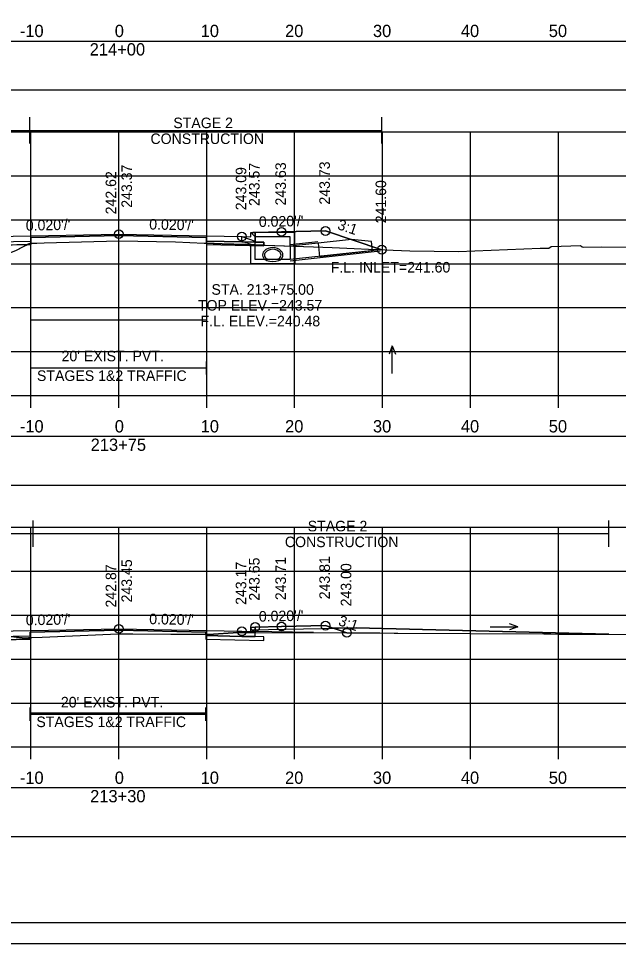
# Model space of a CAD drawing. Extents: x 1369627 to 1374022, y 380035 to 398173.
# Drawn here: x 1372087.1 to 1372155.4, y 383027.1 to 383132.4 of the extents above; entities that cross this region are included whole.
import ezdxf

# ---------------------------------------------------------------- set-up
doc = ezdxf.new("R2010")
doc.units = 0
for name, color, linetype in [('Default', 7, 'Continuous'), ('R_Alt Surface', 7, 'Continuous'), ('R_Axis', 7, 'Continuous'), ('R_Axis Annot', 7, 'Continuous'), ('R_Border', 7, 'Continuous'), ('R_Border Notes', 7, 'Continuous'), ('R_Drive', 7, 'Continuous'), ('R_Exist Surface', 7, 'Continuous'), ('R_Fin Surface', 7, 'Continuous'), ('R_Grid', 7, 'Continuous'), ('R_MOT', 7, 'Continuous'), ('R_No Plot', 7, 'Continuous'), ('R_Water', 7, 'Continuous'), ('R_Water Annot', 7, 'Continuous'), ('R_Xsect Elev', 7, 'Continuous'), ('R_Xsect Slope', 7, 'Continuous'), ('T_Vehicle Path Lt Minor', 7, 'Continuous'), ('T_Vehicle Path Rt', 7, 'Continuous')]:
    doc.layers.add(name, color=color, linetype=linetype)

msp = doc.modelspace()

# ---------------------------------------------------------------- linework, layer by layer
at = {"layer": 'Default'}
for p, q in [((1372088.52, 383091.88), (1372088.52, 383093.38)), ((1372108.52, 383091.88), (1372108.52, 383093.38)), ((1372088.52, 383092.63), (1372108.52, 383092.63)), ((1372088.44, 383052.48), (1372088.44, 383053.98)), ((1372088.44, 383053.23), (1372108.44, 383053.23)), ((1372108.44, 383052.48), (1372108.44, 383053.98))]:
    msp.add_line(p, q, dxfattribs=at)
for points in [[(1371948.53, 383124.28), (1372248.53, 383124.28), (1372248.53, 383129.8), (1371948.53, 383129.8)], [(1371948.53, 383079.29), (1372248.53, 383079.29), (1372248.53, 383084.81), (1371948.53, 383084.81)], [(1371948.53, 383039.31), (1372248.53, 383039.31), (1372248.53, 383044.83), (1371948.53, 383044.83)]]:
    msp.add_lwpolyline(points, close=True, dxfattribs=at)
at = {"layer": 'R_Alt Surface'}
for points in [[(1372083.03, 383108.06), (1372083.03, 383106.96), (1372084.53, 383106.99), (1372088.52, 383107.07), (1372088.52, 383107.49), (1372098.53, 383107.69), (1372108.52, 383107.49), (1372108.52, 383107.07), (1372112.53, 383106.99), (1372114.03, 383106.96), (1372114.03, 383108.06)], [(1372083.03, 383063.14), (1372083.03, 383062.05), (1372084.53, 383062.08), (1372088.44, 383062.15), (1372088.44, 383062.57), (1372098.53, 383062.77), (1372108.44, 383062.57), (1372108.44, 383062.16), (1372112.53, 383062.08), (1372114.03, 383062.05), (1372114.03, 383063.14)]]:
    msp.add_lwpolyline(points, dxfattribs=at)
for points in [[(1372082.03, 383106.94), (1372083.03, 383106.96), (1372084.53, 383106.99), (1372088.52, 383107.07), (1372088.52, 383106.66), (1372082.03, 383106.53)], [(1372115.03, 383106.94), (1372114.03, 383106.96), (1372112.53, 383106.99), (1372108.52, 383107.07), (1372108.52, 383106.66), (1372115.03, 383106.53)], [(1372082.03, 383062.03), (1372083.03, 383062.05), (1372084.53, 383062.08), (1372088.44, 383062.15), (1372088.44, 383061.74), (1372082.03, 383061.61)], [(1372115.03, 383062.03), (1372114.03, 383062.05), (1372112.53, 383062.08), (1372108.44, 383062.16), (1372108.44, 383061.74), (1372115.03, 383061.61)]]:
    msp.add_lwpolyline(points, close=True, dxfattribs=at)
at = {"layer": 'R_Axis'}
for p, q in [((1371948.53, 383089.49), (1372248.53, 383089.49)), ((1372088.53, 383088.09), (1372088.53, 383089.49)), ((1372098.53, 383088.09), (1372098.53, 383089.49)), ((1372108.53, 383088.09), (1372108.53, 383089.49)), ((1372118.53, 383088.09), (1372118.53, 383089.49)), ((1372128.53, 383088.09), (1372128.53, 383089.49)), ((1372138.53, 383088.09), (1372138.53, 383089.49)), ((1372148.53, 383088.09), (1372148.53, 383089.49)), ((1371948.53, 383049.49), (1372248.53, 383049.49)), ((1372088.53, 383048.09), (1372088.53, 383049.49)), ((1372098.53, 383048.09), (1372098.53, 383049.49)), ((1372108.53, 383048.09), (1372108.53, 383049.49)), ((1372118.53, 383048.09), (1372118.53, 383049.49)), ((1372128.53, 383048.09), (1372128.53, 383049.49)), ((1372138.53, 383048.09), (1372138.53, 383049.49)), ((1372148.53, 383048.09), (1372148.53, 383049.49))]:
    msp.add_line(p, q, dxfattribs=at)
at = {"layer": 'R_Border'}
msp.add_line((1372256.71, 383029.49), (1371940.53, 383029.49), dxfattribs=at)
at = {"layer": 'R_Drive'}
for points in [[(1372113.53, 383062.64), (1372113.53, 383062.81), (1372125.53, 383063.05)], [(1372125.53, 383063.05), (1372154.26, 383062.31)]]:
    msp.add_lwpolyline(points, dxfattribs=at)
at = {"layer": 'R_Exist Surface'}
for points in [[(1372086.91, 383106.04), (1372088.12, 383106.66), (1372088.4, 383106.81), (1372090.04, 383106.85), (1372098.52, 383107.11), (1372104.96, 383106.97), (1372108.23, 383106.84), (1372110.29, 383106.76), (1372112.97, 383106.67), (1372120.68, 383106.41), (1372122.81, 383106.34), (1372125.31, 383106.22), (1372126.93, 383106.15), (1372131.63, 383105.95), (1372137.19, 383105.88), (1372146.47, 383106.26), (1372147.45, 383106.28), (1372147.73, 383106.45), (1372147.76, 383106.45), (1372151.04, 383106.58), (1372151.23, 383106.4), (1372151.41, 383106.37), (1372153.47, 383106.4), (1372158.38, 383106.37)], [(1372086.6, 383062.01), (1372087.85, 383061.89), (1372088.27, 383061.9), (1372088.55, 383061.92), (1372088.62, 383061.93), (1372089.81, 383061.99), (1372098.44, 383062.36), (1372100.11, 383062.37), (1372108.72, 383062.3), (1372112.1, 383062.52), (1372128.23, 383062.48), (1372129.86, 383062.44), (1372130, 383062.44), (1372130.09, 383062.44), (1372130.27, 383062.43), (1372146.88, 383062.37), (1372147.11, 383062.36), (1372147.68, 383062.35), (1372148.47, 383062.34), (1372165.64, 383062.24)]]:
    msp.add_lwpolyline(points, dxfattribs=at)
at = {"layer": 'R_Fin Surface'}
for points in [[(1372068.51, 383106.05), (1372075.02, 383108.22), (1372080.02, 383108.12), (1372083.02, 383108.06), (1372083.52, 383108.06), (1372083.53, 383107.56), (1372084.53, 383107.58), (1372086.53, 383107.62), (1372098.53, 383107.86), (1372110.53, 383107.62), (1372112.53, 383107.58), (1372113.53, 383107.56), (1372113.54, 383108.06), (1372114.04, 383108.06), (1372117.04, 383108.12), (1372122.04, 383108.22), (1372128.44, 383106.09)], [(1372071.54, 383062.14), (1372075.02, 383063.3), (1372080.02, 383063.2), (1372083.02, 383063.14), (1372083.52, 383063.14), (1372083.53, 383062.64), (1372084.53, 383062.66), (1372086.53, 383062.7), (1372098.53, 383062.94), (1372110.53, 383062.7), (1372112.53, 383062.66), (1372113.53, 383062.64), (1372113.54, 383063.14), (1372114.04, 383063.14), (1372117.04, 383063.2), (1372122.04, 383063.3), (1372124.48, 383062.49)]]:
    msp.add_lwpolyline(points, dxfattribs=at)
at = {"layer": 'R_Grid'}
for p, q in [((1371948.53, 383119.49), (1372248.53, 383119.49)), ((1372088.53, 383089.49), (1372088.53, 383119.49)), ((1372098.53, 383089.49), (1372098.53, 383119.49)), ((1372108.53, 383089.49), (1372108.53, 383119.49)), ((1372118.53, 383089.49), (1372118.53, 383119.49)), ((1372128.53, 383089.49), (1372128.53, 383119.49)), ((1372138.53, 383089.49), (1372138.53, 383119.49)), ((1372148.53, 383089.49), (1372148.53, 383119.49)), ((1371948.53, 383114.49), (1372248.53, 383114.49)), ((1371948.53, 383109.49), (1372248.53, 383109.49)), ((1371948.53, 383104.49), (1372248.53, 383104.49)), ((1371948.53, 383099.49), (1372248.53, 383099.49)), ((1371948.53, 383094.49), (1372248.53, 383094.49)), ((1371948.53, 383089.49), (1372248.53, 383089.49)), ((1371948.53, 383074.49), (1372248.53, 383074.49)), ((1372088.53, 383049.49), (1372088.53, 383074.49)), ((1372098.53, 383049.49), (1372098.53, 383074.49)), ((1372108.53, 383049.49), (1372108.53, 383074.49)), ((1372118.53, 383049.49), (1372118.53, 383074.49)), ((1372128.53, 383049.49), (1372128.53, 383074.49)), ((1372138.53, 383049.49), (1372138.53, 383074.49)), ((1372148.53, 383049.49), (1372148.53, 383074.49)), ((1371948.53, 383069.49), (1372248.53, 383069.49)), ((1371948.53, 383064.49), (1372248.53, 383064.49)), ((1371948.53, 383059.49), (1372248.53, 383059.49)), ((1371948.53, 383054.49), (1372248.53, 383054.49)), ((1371948.53, 383049.49), (1372248.53, 383049.49))]:
    msp.add_line(p, q, dxfattribs=at)
at = {"layer": 'R_MOT'}
for p, q in [((1372088.4, 383118.17), (1372088.4, 383121.17)), ((1372128.44, 383118.17), (1372128.44, 383121.17)), ((1372068.51, 383119.67), (1372128.44, 383119.67)), ((1372088.77, 383072.28), (1372088.77, 383075.28)), ((1372154.26, 383072.28), (1372154.26, 383075.28)), ((1372053.1, 383073.78), (1372154.26, 383073.78))]:
    msp.add_line(p, q, dxfattribs=at)
at = {"layer": 'R_No Plot'}
for p, q in [((1372121.17, 383106.98), (1372118.04, 383106.64)), ((1372128.27, 383105.93), (1372118.04, 383104.8)), ((1372120.69, 383062.5), (1372113.53, 383062.64)), ((1371720.72, 383027.12), (1372533.33, 383027.12))]:
    msp.add_line(p, q, dxfattribs=at)
msp.add_lwpolyline([(1372174.45, 383234.95), (1372194.07, 383234.95), (1372194.07, 383225.07), (1372210.18, 383225.07), (1372233.38, 383225.07), (1372233.38, 383192.4), (1372256.59, 383192.4), (1372256.71, 383029.49), (1371940.53, 383029.49), (1371940.53, 383234.95)], close=True, dxfattribs=at)
for points in [[(1372088.52, 383098.11), (1372108.52, 383098.11)], [(1372088.44, 383053.36), (1372108.44, 383053.36)]]:
    msp.add_lwpolyline(points, dxfattribs=at)
for centre in [(1372098.53, 383107.86), (1372112.53, 383107.58), (1372117.04, 383108.12), (1372122.04, 383108.22), (1372128.44, 383106.09), (1372122.04, 383063.3), (1372098.53, 383062.94), (1372112.53, 383062.66), (1372114.04, 383063.14), (1372117.04, 383063.2), (1372124.48, 383062.49)]:
    msp.add_circle(centre, 0.5, dxfattribs=at)
at = {"layer": 'R_Water'}
for p, q in [((1372113.71, 383107.9), (1372113.79, 383108.06)), ((1372118.54, 383108.06), (1372113.79, 383108.06)), ((1372118.54, 383106.56), (1372118.54, 383108.06)), ((1372112.54, 383107.58), (1372114.04, 383107.06)), ((1372112.54, 383107.05), (1372113.54, 383106.7)), ((1372113.71, 383107.9), (1372114.04, 383107.56)), ((1372118.04, 383107.56), (1372114.04, 383107.56)), ((1372114.04, 383106.56), (1372114.04, 383107.06)), ((1372118.04, 383106.56), (1372118.04, 383107.56)), ((1372113.54, 383106.56), (1372113.54, 383106.7)), ((1372121.19, 383106.82), (1372118.04, 383106.47)), ((1372128.27, 383106.09), (1372118.04, 383104.97))]:
    msp.add_line(p, q, dxfattribs=at)
for points in [[(1372112.54, 383107.05), (1372112.54, 383107.58)], [(1372118.54, 383106.56), (1372118.54, 383104.47), (1372116.04, 383104.47), (1372113.54, 383104.47), (1372113.54, 383106.56)], [(1372118.04, 383106.56), (1372118.04, 383104.97), (1372116.04, 383104.97), (1372114.04, 383104.97), (1372114.04, 383106.56)]]:
    msp.add_lwpolyline(points, dxfattribs=at)
msp.add_lwpolyline([(1372121.19, 383106.82), (1372121.35, 383105.33), (1372127.4, 383105.99), (1372127.29, 383107.02), (1372125, 383107.23)], close=True, dxfattribs=at)
for centre, radius, start, end in [((1372115.53, 383105.48), 0.646, 136.3515, 253.9529), ((1372116.04, 383104.99), 1.35, 43.6485, 136.3515), ((1372116.04, 383104.99), 1.15, 43.6485, 136.3515), ((1372116.55, 383105.48), 0.646, 286.0471, 43.6485), ((1372115.53, 383105.48), 0.438, 136.3515, 253.9529), ((1372116.04, 383107.26), 2.5, 253.9529, 286.0471), ((1372116.04, 383107.26), 2.29, 253.9529, 286.0471), ((1372116.55, 383105.48), 0.438, 286.0471, 43.6485)]:
    msp.add_arc(centre, radius, start, end, dxfattribs=at)
at = {"layer": 'R_Water Annot'}
for p, q in [((1372129.64, 383095.15), (1372129.29, 383094.19)), ((1372129.64, 383092.01), (1372129.64, 383095.15)), ((1372129.64, 383095.15), (1372129.99, 383094.19)), ((1372140.78, 383063.17), (1372143.92, 383063.17)), ((1372143.92, 383063.17), (1372142.96, 383063.52)), ((1372143.92, 383063.17), (1372142.96, 383062.82))]:
    msp.add_line(p, q, dxfattribs=at)
at = {"layer": 'R_Xsect Elev'}
for p, q in [((1372098.53, 383107.11), (1372098.53, 383117.11)), ((1372098.53, 383062.36), (1372098.53, 383072.36))]:
    msp.add_line(p, q, dxfattribs=at)
at = {"layer": 'T_Vehicle Path Lt Minor'}
for p, q in [((1372125.53, 383063.05), (1372122.95, 383063)), ((1372122.95, 383063), (1372124.48, 383062.49)), ((1372154.26, 383062.31), (1372125.53, 383063.05)), ((1372124.48, 383062.49), (1372128.23, 383062.48))]:
    msp.add_line(p, q, dxfattribs=at)
msp.add_lwpolyline([(1372128.23, 383062.48), (1372129.86, 383062.44), (1372130, 383062.44), (1372130.09, 383062.44), (1372130.27, 383062.43), (1372146.88, 383062.37), (1372147.11, 383062.36), (1372147.68, 383062.35), (1372148.47, 383062.34), (1372154.26, 383062.31)], dxfattribs=at)
at = {"layer": 'T_Vehicle Path Rt'}
for p, q in [((1372114.04, 383108.06), (1372114.03, 383106.96)), ((1372088.52, 383107.07), (1372088.52, 383106.82)), ((1372108.52, 383106.83), (1372108.52, 383107.07)), ((1372088.11, 383106.65), (1372082.03, 383106.53)), ((1372088.4, 383106.81), (1372088.12, 383106.66)), ((1372088.12, 383106.65), (1372088.52, 383106.66)), ((1372088.52, 383106.82), (1372088.4, 383106.81)), ((1372088.52, 383106.66), (1372088.52, 383106.82)), ((1372108.52, 383106.83), (1372108.52, 383106.66)), ((1372115.03, 383106.6), (1372120.68, 383106.41)), ((1372114.04, 383063.14), (1372114.03, 383062.52)), ((1372088.44, 383062.15), (1372088.44, 383061.91)), ((1372108.44, 383062.31), (1372108.44, 383062.57)), ((1372108.44, 383062.31), (1372108.44, 383062.16)), ((1372112.53, 383062.08), (1372108.44, 383062.16)), ((1372114.03, 383062.05), (1372112.53, 383062.08)), ((1372114.03, 383062.52), (1372124.48, 383062.49))]:
    msp.add_line(p, q, dxfattribs=at)
for points in [[(1372128.44, 383106.09), (1372122.04, 383108.22), (1372117.04, 383108.12), (1372114.04, 383108.06)], [(1372108.52, 383107.07), (1372108.52, 383107.49), (1372098.53, 383107.69), (1372088.52, 383107.49), (1372088.52, 383107.07)], [(1372088.52, 383106.82), (1372090.04, 383106.85), (1372098.52, 383107.11), (1372104.96, 383106.97), (1372108.23, 383106.84), (1372108.52, 383106.83)], [(1372114.03, 383106.96), (1372115.03, 383106.94), (1372115.03, 383106.6)], [(1372068.51, 383106.05), (1372069.1, 383106.06), (1372070.6, 383106.08), (1372074.03, 383106.27), (1372076.34, 383106.43), (1372076.88, 383106.34), (1372078.33, 383106.21), (1372079.95, 383105.07), (1372080.29, 383104.85), (1372080.76, 383104.63), (1372081.9, 383104.11), (1372083.39, 383104.59), (1372084.19, 383104.9), (1372085.02, 383105.26), (1372086.91, 383106.04), (1372087.76, 383106.48), (1372088.11, 383106.65)], [(1372088.12, 383106.66), (1372088.12, 383106.65)], [(1372115.03, 383106.6), (1372112.97, 383106.67), (1372110.29, 383106.76), (1372108.52, 383106.83)], [(1372108.52, 383106.66), (1372115.03, 383106.53), (1372115.03, 383106.6)], [(1372120.68, 383106.41), (1372122.81, 383106.34), (1372125.31, 383106.22), (1372126.93, 383106.15), (1372128.44, 383106.09)], [(1372108.44, 383062.57), (1372098.53, 383062.77), (1372088.44, 383062.57), (1372088.44, 383062.15)], [(1372124.48, 383062.49), (1372122.04, 383063.3), (1372117.04, 383063.2), (1372114.04, 383063.14)], [(1372083.03, 383062.05), (1372082.03, 383062.03), (1372082.03, 383061.61), (1372088.44, 383061.74), (1372088.44, 383061.91)], [(1372088.44, 383061.91), (1372088.27, 383061.9), (1372087.85, 383061.89), (1372086.6, 383062.01), (1372085.92, 383062.02), (1372083.7, 383062.06)], [(1372088.44, 383061.91), (1372088.55, 383061.92), (1372088.62, 383061.93), (1372089.81, 383061.99), (1372098.44, 383062.36), (1372100.11, 383062.37), (1372108.44, 383062.31)], [(1372108.44, 383062.16), (1372112.53, 383062.08), (1372114.03, 383062.05), (1372114.03, 383062.52)], [(1372114.03, 383062.52), (1372112.1, 383062.52), (1372108.72, 383062.3), (1372108.44, 383062.31)], [(1372108.44, 383062.16), (1372108.44, 383061.74), (1372115.03, 383061.61), (1372115.03, 383062.03), (1372114.03, 383062.05)]]:
    msp.add_lwpolyline(points, dxfattribs=at)

# ---------------------------------------------------------------- texts
at = {"layer": 'R_Axis Annot'}
for s, height, p in [('-10', 1.4, (1372087.27, 383130.29)), ('0', 1.4, (1372098.07, 383130.29)), ('10', 1.4, (1372107.84, 383130.29)), ('20', 1.4, (1372117.44, 383130.29)), ('30', 1.4, (1372127.44, 383130.29)), ('40', 1.4, (1372137.44, 383130.29)), ('50', 1.4, (1372147.44, 383130.29)), ('214+00', 1.4, (1372095.22, 383128.19)), ("20' EXIST. PVT.", 1.2, (1372092.02, 383093.39)), ('STAGES 1&2 TRAFFIC', 1.2, (1372089.22, 383091.15)), ('-10', 1.4, (1372087.27, 383085.29)), ('0', 1.4, (1372098.07, 383085.29)), ('10', 1.4, (1372107.84, 383085.29)), ('20', 1.4, (1372117.44, 383085.29)), ('30', 1.4, (1372127.44, 383085.29)), ('40', 1.4, (1372137.44, 383085.29)), ('50', 1.4, (1372147.44, 383085.29)), ('213+75', 1.4, (1372095.33, 383083.19)), ("20' EXIST. PVT.", 1.2, (1372091.94, 383053.99)), ('STAGES 1&2 TRAFFIC', 1.2, (1372089.15, 383051.75)), ('-10', 1.4, (1372087.27, 383045.29)), ('0', 1.4, (1372098.07, 383045.29)), ('10', 1.4, (1372107.84, 383045.29)), ('20', 1.4, (1372117.44, 383045.29)), ('30', 1.4, (1372127.44, 383045.29)), ('40', 1.4, (1372137.44, 383045.29)), ('50', 1.4, (1372147.44, 383045.29)), ('213+30', 1.4, (1372095.27, 383043.19))]:
    msp.add_text(s, height=height, dxfattribs=at).set_placement(p)
at = {"layer": 'R_Border Notes'}
msp.add_text('F.L. INLET=241.60', height=1.2, dxfattribs=at).set_placement((1372122.64, 383103.49))
at = {"layer": 'R_MOT'}
for s, p in [('STAGE 2', (1372104.73, 383119.92)), ('CONSTRUCTION', (1372102.13, 383118.12)), ('STAGE 2', (1372120.02, 383074.03)), ('CONSTRUCTION', (1372117.42, 383072.23))]:
    msp.add_text(s, height=1.2, dxfattribs=at).set_placement(p)
at = {"layer": 'R_Water Annot'}
for s, p in [('STA. 213+75.00', (1372109.07, 383100.96)), ('TOP ELEV.=243.57', (1372107.53, 383099.16)), ('F.L. ELEV.=240.48', (1372107.83, 383097.36))]:
    msp.add_text(s, height=1.2, dxfattribs=at).set_placement(p)
at = {"layer": 'R_Xsect Elev'}
for s, p in [('243.37', (1372100.03, 383110.86)), ('243.09', (1372113.03, 383110.58)), ('243.57', (1372114.54, 383111.06)), ('243.63', (1372117.54, 383111.12)), ('243.73', (1372122.54, 383111.22)), ('242.62', (1372098.23, 383110.11)), ('241.60', (1372128.94, 383109.09)), ('243.81', (1372122.54, 383066.3)), ('242.87', (1372098.23, 383065.36)), ('243.45', (1372100.03, 383065.94)), ('243.17', (1372113.03, 383065.66)), ('243.65', (1372114.54, 383066.14)), ('243.71', (1372117.54, 383066.2)), ('243.00', (1372124.98, 383065.49))]:
    msp.add_text(s, height=1.2, rotation=90, dxfattribs=at).set_placement(p)
at = {"layer": 'R_Xsect Slope'}
for s, rotation, p in [("0.020'/'", 1.1458, (1372087.96, 383108.25)), ("0.020'/'", 358.8542, (1372101.98, 383108.39)), ("0.020'/'", 1.1458, (1372114.47, 383108.67)), ('3:1', 341.5668, (1372123.32, 383108.45)), ("0.020'/'", 1.1458, (1372114.47, 383063.75)), ("0.020'/'", 1.1458, (1372087.96, 383063.33)), ("0.020'/'", 358.8542, (1372101.98, 383063.47)), ('3:1', 341.5668, (1372123.42, 383063.37))]:
    msp.add_text(s, height=1.2, rotation=rotation, dxfattribs=at).set_placement(p)

doc.saveas('drawing.dxf')
